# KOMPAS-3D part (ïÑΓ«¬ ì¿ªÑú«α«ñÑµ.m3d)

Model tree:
1. Эскиз:2
2. Операция выдавливания:1
     Расстояние 1 = 37; Угол 1 = 4
3. Эскиз:3
4. Вырезать элемент выдавливания:1
     Расстояние 2 = 37; Угол 2 = 1.91; Расстояние 1 = 10
5. Оболочка:2
     Толщина стенки 2 = 1
6. Эскиз:8
7. Вырезать элемент выдавливания:4
     Расстояние 2 = 11.2339; Расстояние 1 = 11.2339
8. Эскиз:10
9. Операция выдавливания:4
     Расстояние 1 = 1; Угол 2 = 1.98
